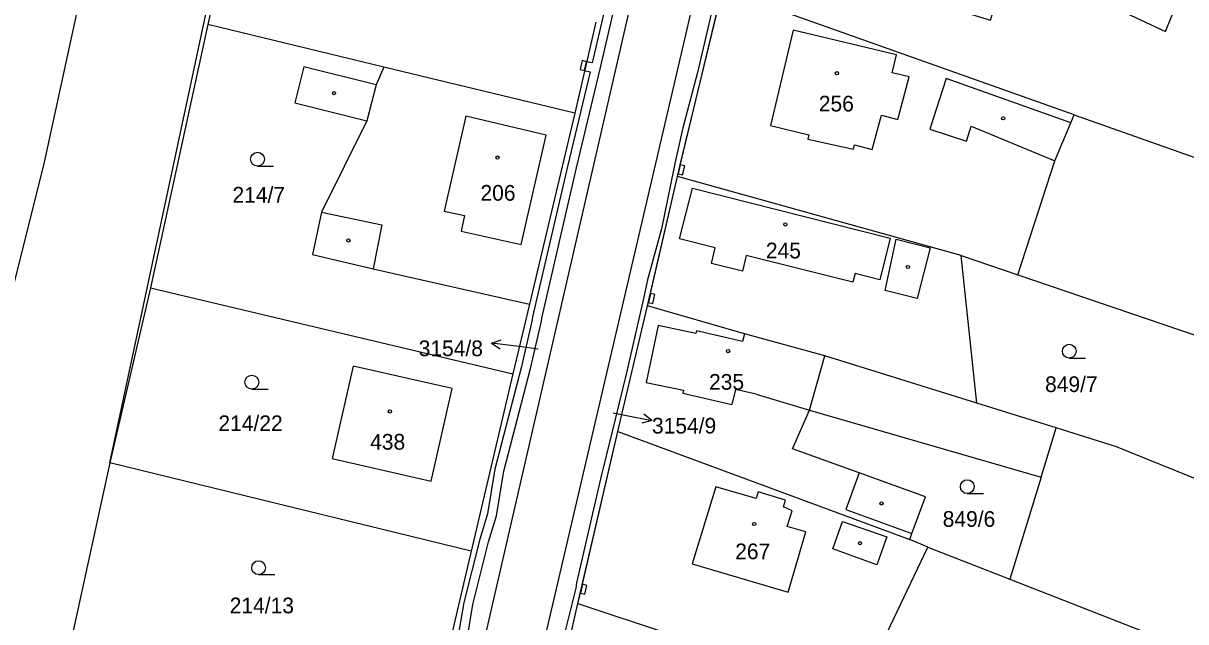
# Model space of a CAD drawing. Extents: x -776734 to -748832, y -1118122 to -976986.
# Drawn here: x -752850.8 to -752725, y -1114718.3 to -1114653.4 of the extents above; entities that cross this region are included whole.
import ezdxf

# ---------------------------------------------------------------- set-up
doc = ezdxf.new("R2010")
doc.units = 0
for name, color, linetype in [('KM_Hranice parcel', 7, 'Continuous'), ('KM_Parcelní čísla', 7, 'Continuous'), ('KM_Pop  PČ popisy', 7, 'Continuous'), ('KM_Vnitřní kresba', 7, 'Continuous'), ('KM_Věcná břemena k části', 7, 'Continuous'), ('KM_Značky budov', 7, 'Continuous'), ('KM_Značky kultur', 7, 'Continuous')]:
    doc.layers.add(name, color=color, linetype=linetype)

msp = doc.modelspace()

# ---------------------------------------------------------------- linework, layer by layer
at = {"layer": 'KM_Hranice parcel'}
for p, q in [((-752779.02, -1114654.54), (-752772.95, -1114628.04)), ((-752826.69, -1114634.91), (-752830.82, -1114653.56)), ((-752779.98, -1114670.03), (-752775.12, -1114649.81)), ((-752737.05, -1114663.35), (-752775.12, -1114649.81)), ((-752830.82, -1114653.56), (-752837.03, -1114682.11)), ((-752811.76, -1114658.18), (-752830.82, -1114653.56)), ((-752788.83, -1114653.31), (-752791.09, -1114663.19)), ((-752811.76, -1114658.18), (-752812.6, -1114660.1)), ((-752791.09, -1114663.19), (-752811.76, -1114658.18)), ((-752791.09, -1114663.19), (-752796, -1114683.88)), ((-752737.05, -1114663.35), (-752692.81, -1114679.08)), ((-752783.21, -1114684.04), (-752779.98, -1114670.03)), ((-752749.28, -1114678.6), (-752779.98, -1114670.03)), ((-752749.28, -1114678.6), (-752743.13, -1114680.69)), ((-752747.59, -1114694.59), (-752749.28, -1114678.6)), ((-752837.03, -1114682.11), (-752841.41, -1114701.06)), ((-752837.03, -1114682.11), (-752797.79, -1114691.42)), ((-752796, -1114683.88), (-752797.79, -1114691.42)), ((-752786.43, -1114697.67), (-752783.21, -1114684.04)), ((-752797.79, -1114691.42), (-752802.31, -1114710.63)), ((-752738.98, -1114697.27), (-752747.59, -1114694.59)), ((-752790.75, -1114716.31), (-752786.43, -1114697.67)), ((-752786.43, -1114697.67), (-752754.83, -1114709.37)), ((-752740.61, -1114702.6), (-752738.98, -1114697.27)), ((-752841.41, -1114701.06), (-752845.55, -1114720.08)), ((-752802.31, -1114710.63), (-752841.41, -1114701.06)), ((-752740.61, -1114702.6), (-752743.99, -1114713.66)), ((-752752.87, -1114710.19), (-752754.83, -1114709.37)), ((-752802.31, -1114710.63), (-752805.39, -1114723.86)), ((-752752.87, -1114710.19), (-752743.99, -1114713.66)), ((-752743.99, -1114713.66), (-752729.9, -1114719.17)), ((-752792.05, -1114722.04), (-752790.75, -1114716.31))]:
    msp.add_line(p, q, dxfattribs=at)
for points in [[(-752877.51, -1114796.45), (-752864.37, -1114734.66), (-752855.23, -1114695.41), (-752848.48, -1114668.5), (-752842.28, -1114639.9), (-752832.25, -1114590.62), (-752814.67, -1114513.35), (-752808.19, -1114483.16), (-752800.05, -1114438.6), (-752784.13, -1114357.8), (-752769.94, -1114301.29), (-752757.23, -1114242.84)], [(-752841.41, -1114701.06), (-752813.72, -1114571.41), (-752793.81, -1114484.96), (-752789.11, -1114457.63), (-752769.97, -1114355.06), (-752767.59, -1114346.94)], [(-752779.18, -1114626.02), (-752784.63, -1114649.56), (-752785.56, -1114653.59)], [(-752773.87, -1114644.63), (-752746.11, -1114653.11), (-752744.07, -1114646.38), (-752727.14, -1114654.34), (-752725.24, -1114649.58)], [(-752785.56, -1114653.59), (-752802.93, -1114729.01), (-752805.4, -1114739.76), (-752817.12, -1114789.2), (-752834.89, -1114866.39), (-752854.22, -1114948.74), (-752882.92, -1115072.56), (-752893.17, -1115116.65), (-752898.67, -1115140.84), (-752901.21, -1115152.69), (-752902.77, -1115162.03), (-752904.54, -1115175.28), (-752905.59, -1115186.25), (-752907.24, -1115206.15), (-752907.97, -1115217.91), (-752910.76, -1115260.79), (-752912.73, -1115288.36)], [(-752893.27, -1115146.65), (-752892.2, -1115141.48), (-752884.4, -1115107.23), (-752882.98, -1115101.01), (-752882.52, -1115099.06), (-752878.08, -1115079.92), (-752848.33, -1114951.79), (-752828.79, -1114868.65), (-752810.45, -1114789.66), (-752799.15, -1114740.86), (-752796.77, -1114730.63), (-752779.02, -1114654.54)], [(-752812.6, -1114660.1), (-752820.42, -1114658.16), (-752821.4, -1114662.07)], [(-752821.4, -1114662.07), (-752813.6, -1114664.01), (-752818.5, -1114673.9), (-752819.48, -1114678.49), (-752812.91, -1114680.06), (-752796, -1114683.88)], [(-752743.13, -1114680.69), (-752739.12, -1114668.34), (-752737.41, -1114664.21), (-752737.05, -1114663.35)], [(-752743.13, -1114680.69), (-752722.16, -1114687.84), (-752718.91, -1114689.13)], [(-752747.59, -1114694.59), (-752764.04, -1114689.46), (-752772.71, -1114687.1), (-752783.21, -1114684.04)], [(-752815.09, -1114690.57), (-752817.36, -1114700.59), (-752806.63, -1114703.05), (-752804.35, -1114692.99), (-752815.09, -1114690.57)], [(-752754.83, -1114709.37), (-752754.6, -1114708.73), (-752753.15, -1114704.76), (-752760.3, -1114702.15), (-752767.52, -1114699.54), (-752765.69, -1114695.35), (-752740.61, -1114702.6)], [(-752723.18, -1114703.07), (-752732.45, -1114699.31), (-752738.98, -1114697.27)], [(-752790.75, -1114716.31), (-752760.56, -1114726.35), (-752752.87, -1114710.19)]]:
    msp.add_lwpolyline(points, dxfattribs=at)
at = {"layer": 'KM_Pop  PČ popisy'}
for p, q in [((-752800.099, -1114688.104), (-752799.044, -1114687.729)), ((-752797.12, -1114688.47), (-752800.099, -1114688.104)), ((-752800.099, -1114688.104), (-752799.166, -1114688.723)), ((-752795.07, -1114688.74), (-752797.12, -1114688.47)), ((-752786.95, -1114695.64), (-752785.69, -1114695.89)), ((-752785.69, -1114695.89), (-752782.744, -1114696.463)), ((-752782.744, -1114696.463), (-752783.823, -1114696.763)), ((-752782.744, -1114696.463), (-752783.632, -1114695.78))]:
    msp.add_line(p, q, dxfattribs=at)
at = {"layer": 'KM_Vnitřní kresba'}
for p, q in [((-752767.45, -1114654.2), (-752769.9, -1114664.51)), ((-752756.28, -1114656.85), (-752767.45, -1114654.2)), ((-752756.74, -1114658.81), (-752756.28, -1114656.85)), ((-752754.9, -1114659.25), (-752756.74, -1114658.81)), ((-752812.6, -1114660.1), (-752813.6, -1114664.01)), ((-752756.12, -1114663.86), (-752754.9, -1114659.25)), ((-752750.88, -1114659.43), (-752752.66, -1114664.92)), ((-752737.41, -1114664.21), (-752750.88, -1114659.43)), ((-752802.9, -1114663.49), (-752805.22, -1114673.79)), ((-752794.18, -1114665.57), (-752802.9, -1114663.49)), ((-752758.9, -1114667.12), (-752757.88, -1114663.38)), ((-752757.88, -1114663.38), (-752756.12, -1114663.86)), ((-752769.9, -1114664.51), (-752765.77, -1114665.51)), ((-752752.66, -1114664.92), (-752748.71, -1114666.2)), ((-752748.71, -1114666.2), (-752748.18, -1114664.58)), ((-752748.18, -1114664.58), (-752739.12, -1114668.34)), ((-752796.9, -1114677.42), (-752794.18, -1114665.57)), ((-752765.77, -1114665.51), (-752765.88, -1114665.99)), ((-752765.88, -1114665.99), (-752760.91, -1114667.09)), ((-752760.91, -1114667.09), (-752760.81, -1114666.61)), ((-752760.81, -1114666.61), (-752758.9, -1114667.12)), ((-752779.76, -1114676.81), (-752778.36, -1114671.31)), ((-752778.36, -1114671.31), (-752756.95, -1114676.73)), ((-752818.5, -1114673.9), (-752811.96, -1114675.27)), ((-752805.22, -1114673.79), (-752803.02, -1114674.28)), ((-752811.96, -1114675.27), (-752812.91, -1114680.06)), ((-752803.02, -1114674.28), (-752803.39, -1114675.97)), ((-752803.39, -1114675.97), (-752796.9, -1114677.42)), ((-752775.89, -1114677.77), (-752779.76, -1114676.81)), ((-752776.31, -1114679.47), (-752775.89, -1114677.77)), ((-752756.95, -1114676.73), (-752758.07, -1114681.22)), ((-752757.5, -1114682.4), (-752756.29, -1114676.82)), ((-752756.29, -1114676.82), (-752752.64, -1114677.75)), ((-752752.64, -1114677.75), (-752754.03, -1114683.27)), ((-752772.53, -1114678.61), (-752772.95, -1114680.3)), ((-752760.99, -1114681.47), (-752772.53, -1114678.61)), ((-752772.95, -1114680.3), (-752776.31, -1114679.47)), ((-752760.76, -1114680.55), (-752760.99, -1114681.47)), ((-752758.07, -1114681.22), (-752760.76, -1114680.55)), ((-752754.03, -1114683.27), (-752757.5, -1114682.4)), ((-752782.07, -1114686.18), (-752783.37, -1114692.36)), ((-752777.99, -1114687.06), (-752782.07, -1114686.18)), ((-752777.93, -1114686.77), (-752777.99, -1114687.06)), ((-752772.95, -1114687.91), (-752777.93, -1114686.77)), ((-752772.71, -1114687.1), (-752772.95, -1114687.91)), ((-752765.69, -1114695.35), (-752764.04, -1114689.46)), ((-752783.37, -1114692.36), (-752779.34, -1114693.2)), ((-752779.34, -1114693.2), (-752779.41, -1114693.52)), ((-752779.41, -1114693.52), (-752774.08, -1114694.73)), ((-752773.71, -1114693.1), (-752774.08, -1114694.73)), ((-752771.45, -1114693.61), (-752773.71, -1114693.1)), ((-752771.45, -1114693.61), (-752765.69, -1114695.35)), ((-752760.3, -1114702.15), (-752761.75, -1114706.1)), ((-752775.82, -1114703.67), (-752778.37, -1114711.99)), ((-752771.45, -1114704.93), (-752775.82, -1114703.67)), ((-752771.23, -1114704.19), (-752771.45, -1114704.93)), ((-752768.28, -1114705.1), (-752771.23, -1114704.19)), ((-752768.5, -1114705.84), (-752768.28, -1114705.1)), ((-752767.58, -1114706.25), (-752768.5, -1114705.84)), ((-752768.09, -1114707.96), (-752767.58, -1114706.25)), ((-752761.75, -1114706.1), (-752754.6, -1114708.73)), ((-752766.09, -1114708.54), (-752768.09, -1114707.96)), ((-752763.16, -1114710.38), (-752762.11, -1114707.43)), ((-752762.11, -1114707.43), (-752757.31, -1114709.06)), ((-752768, -1114715.08), (-752766.09, -1114708.54)), ((-752757.31, -1114709.06), (-752758.41, -1114712.1)), ((-752758.41, -1114712.1), (-752763.16, -1114710.38)), ((-752778.37, -1114711.99), (-752768, -1114715.08))]:
    msp.add_line(p, q, dxfattribs=at)
at = {"layer": 'KM_Věcná břemena k části'}
for points in [[(-752787.02, -1114648.27), (-752789.21, -1114657.72), (-752789.81, -1114657.6), (-752790.03, -1114658.57), (-752789.44, -1114658.69), (-752791.89, -1114668.94), (-752795.67, -1114685.24), (-752795.69, -1114685.57), (-752796.87, -1114690.61), (-752799.76, -1114701.74), (-752800.55, -1114706.57), (-752801.38, -1114709.34), (-752803.11, -1114716.19), (-752803.84, -1114720.59)], [(-752802.86, -1114720.8), (-752802.13, -1114716.4), (-752800.42, -1114709.62), (-752799.57, -1114706.81), (-752798.78, -1114701.96), (-752795.89, -1114690.83), (-752794.69, -1114685.72), (-752794.67, -1114685.37), (-752790.9, -1114669.1), (-752788.3, -1114658.23), (-752786.21, -1114649.21)], [(-752775.56, -1114649.14), (-752777.82, -1114658.76), (-752779.4, -1114664.76), (-752780.28, -1114668.62), (-752780.37, -1114669.17), (-752781.71, -1114675.7), (-752783.22, -1114681.23), (-752783.63, -1114683.1), (-752785.52, -1114691.47), (-752787.04, -1114697.66), (-752788.3, -1114702.79), (-752790.89, -1114714.07), (-752790.97, -1114714.62), (-752792.44, -1114720.56)], [(-752790.49, -1114715.19), (-752790.26, -1114714.21), (-752786.43, -1114697.67), (-752783.21, -1114684.04), (-752783.13, -1114683.7), (-752782.91, -1114682.73), (-752779.98, -1114670.03), (-752779.91, -1114669.74), (-752779.68, -1114668.77), (-752775.12, -1114649.81)], [(-752815.59, -1114822.06), (-752810.36, -1114800.13), (-752805.1, -1114778.01), (-752805.14, -1114777.44), (-752805.1, -1114777.28), (-752804.87, -1114776.31), (-752799.87, -1114755.43), (-752795.92, -1114738.75), (-752794.27, -1114731.61), (-752794.04, -1114730.64), (-752792.05, -1114722.04), (-752790.75, -1114716.31), (-752790.49, -1114715.19)]]:
    msp.add_lwpolyline(points, dxfattribs=at)
for points in [[(-752790.52, -1114658.46), (-752790.03, -1114658.57), (-752789.81, -1114657.6), (-752790.3, -1114657.49)], [(-752779.68, -1114668.77), (-752779.91, -1114669.74), (-752779.42, -1114669.86), (-752779.19, -1114668.88)], [(-752782.42, -1114682.84), (-752782.91, -1114682.73), (-752783.13, -1114683.7), (-752782.64, -1114683.81)], [(-752789.78, -1114714.33), (-752790.26, -1114714.21), (-752790.49, -1114715.19), (-752790, -1114715.3)]]:
    msp.add_lwpolyline(points, close=True, dxfattribs=at)
at = {"layer": 'KM_Značky budov'}
for centre in [(-752762.7268, -1114658.8492), (-752817.1468, -1114661.0092), (-752744.7168, -1114663.7392), (-752799.4568, -1114667.9892), (-752768.3068, -1114675.2292), (-752815.5868, -1114676.9692), (-752755.0368, -1114679.8392), (-752774.4968, -1114688.9492), (-752811.0968, -1114695.4892), (-752757.8968, -1114705.4592), (-752771.6668, -1114707.6892), (-752760.2268, -1114709.7592)]:
    msp.add_circle(centre, 0.175, dxfattribs=at)
at = {"layer": 'KM_Značky kultur'}
for p, q in [((-752825.433, -1114668.92), (-752823.683, -1114668.92)), ((-752737.573, -1114689.72), (-752735.823, -1114689.72)), ((-752826.043, -1114693.07), (-752824.293, -1114693.07)), ((-752748.613, -1114704.39), (-752746.863, -1114704.39)), ((-752825.313, -1114713.17), (-752823.563, -1114713.17))]:
    msp.add_line(p, q, dxfattribs=at)
for centre in [(-752825.4329, -1114668.1698), (-752737.5729, -1114688.9698), (-752826.0429, -1114692.3198), (-752748.6129, -1114703.6398), (-752825.3129, -1114712.4198)]:
    msp.add_circle(centre, 0.75, dxfattribs=at)

# ---------------------------------------------------------------- texts
at = {"layer": 'KM_Parcelní čísla'}
for s, p in [('256', (-752764.68, -1114662.99)), ('214/7', (-752828.14, -1114672.87)), ('206', (-752801.3, -1114672.66)), ('245', (-752770.41, -1114678.91)), ('3154/8', (-752807.985, -1114689.504)), ('235', (-752776.56, -1114693.14)), ('849/7', (-752740.19, -1114693.39)), ('214/22', (-752829.66, -1114697.62)), ('3154/9', (-752782.74, -1114697.884)), ('438', (-752813.24, -1114699.63)), ('849/6', (-752751.27, -1114707.99)), ('267', (-752773.73, -1114711.5)), ('214/13', (-752828.44, -1114717.36))]:
    msp.add_text(s, height=1.7, dxfattribs=at).set_placement(p)

doc.saveas('drawing.dxf')
